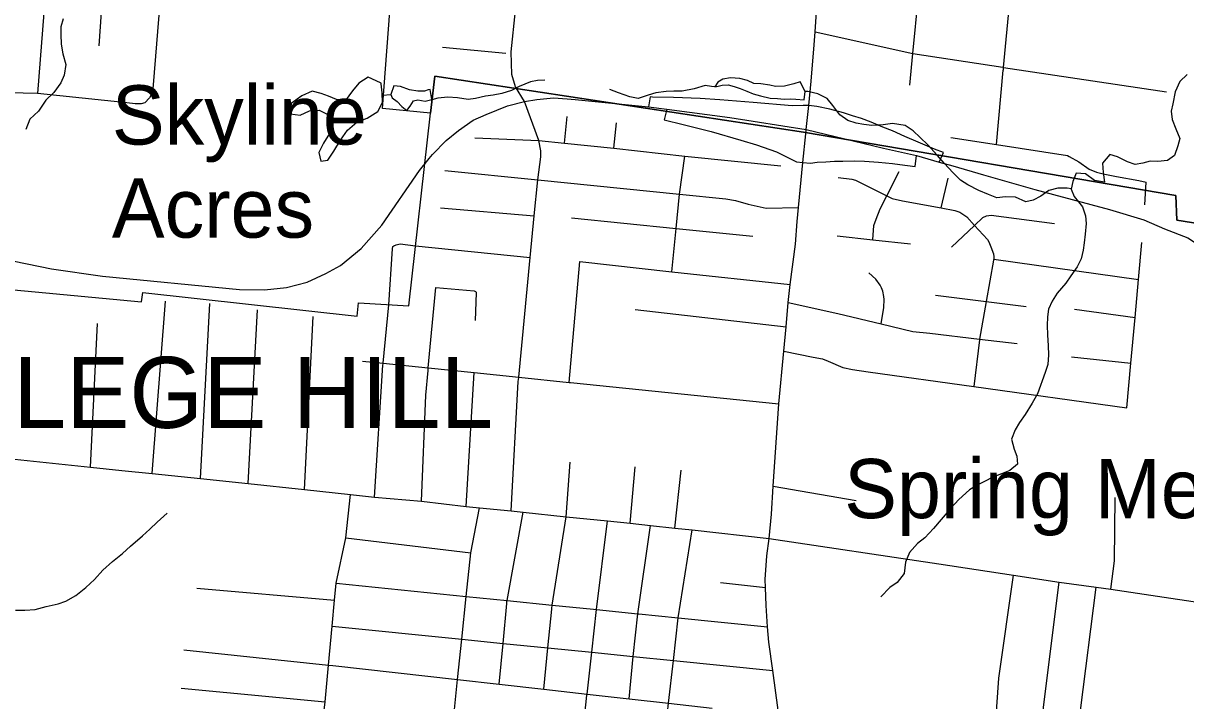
# Model space of a CAD drawing. Extents: x 0 to 69.5, y -4.5 to 22.
# Drawn here: x 5.421 to 6.973, y 15.023 to 15.927 of the extents above; entities that cross this region are included whole.
import ezdxf

# ---------------------------------------------------------------- set-up
doc = ezdxf.new("R2010")
doc.units = 0
for name, color, linetype in [('GM_X_City_Street', 7, 'Continuous'), ('GM_X_Corporation', 7, 'Continuous'), ('GM_X_Corporation_Text', 7, 'Continuous'), ('GM_X_Interchange_Ramps', 7, 'Continuous'), ('GM_X_Minor_Lake', 7, 'Continuous'), ('GM_X_Minor_River', 7, 'Continuous'), ('GM_X_State_Route', 7, 'Continuous'), ('GM_X_Township_Subdivision', 7, 'Continuous'), ('GM_X_Unincorporated_Text', 7, 'Continuous'), ('GM_X_US_Route', 7, 'Continuous')]:
    doc.layers.add(name, color=color, linetype=linetype)

msp = doc.modelspace()

# ---------------------------------------------------------------- linework, layer by layer
at = {"layer": 'GM_X_City_Street'}
for points in [[(6.0782, 15.8417), (6.073, 15.8584), (6.0723, 15.8887), (6.0782, 15.9436), (6.0848, 16.0117), (6.0879, 16.0415), (6.0881, 16.0439), (6.0947, 16.1212), (6.1032, 16.2159)], [(6.7292, 15.8641), (6.7295, 15.8678), (6.7378, 15.9562), (6.7561, 16.1506), (6.7562, 16.1518), (6.7563, 16.1521)], [(6.6042, 15.8442), (6.6083, 15.8863), (6.6157, 15.9635)], [(6.4779, 15.9151), (6.6083, 15.8863), (6.7283, 15.868), (6.7295, 15.8678), (6.9469, 15.8351)], [(5.9805, 15.8947), (6.0649, 15.8869)], [(6.7198, 15.7648), (6.7291, 15.864), (6.7292, 15.8641)], [(6.0823, 15.4541), (6.0823, 15.4546), (6.0976, 15.6143), (6.1029, 15.6697), (6.1076, 15.718), (6.1118, 15.7486), (6.1118, 15.7565), (6.1092, 15.7703), (6.0898, 15.8223), (6.0782, 15.8417)], [(6.1433, 15.7667), (6.147, 15.8022)], [(6.2091, 15.7601), (6.2127, 15.794)], [(6.0239, 15.7737), (6.1092, 15.7703), (6.1433, 15.7667), (6.2091, 15.7601), (6.3038, 15.7493), (6.432, 15.7365)], [(6.659, 15.7742), (6.7198, 15.7648), (6.8147, 15.7502), (6.8169, 15.749)], [(6.2868, 15.5953), (6.2923, 15.6531), (6.2967, 15.6989), (6.3038, 15.7493)], [(6.8169, 15.749), (6.8301, 15.7417), (6.8435, 15.7319), (6.8534, 15.7281), (6.8622, 15.7258), (6.88, 15.7225), (6.9102, 15.7169), (6.9197, 15.7146)], [(5.9837, 15.7305), (6.1076, 15.718), (6.2967, 15.6989), (6.3588, 15.6926), (6.3717, 15.6904), (6.3887, 15.6855), (6.4125, 15.68), (6.4555, 15.6809)], [(6.5085, 15.7208), (6.527, 15.7186), (6.5319, 15.7173), (6.5737, 15.6965), (6.5808, 15.693), (6.5944, 15.6897), (6.646, 15.6804), (6.6645, 15.6771), (6.6709, 15.6747), (6.6802, 15.6684), (6.6907, 15.6571), (6.7081, 15.6382), (6.7096, 15.6353), (6.7124, 15.6286), (6.716, 15.619), (6.7165, 15.615), (6.7163, 15.6122), (6.7162, 15.6106), (6.7064, 15.5556), (6.6974, 15.5054), (6.6972, 15.5043), (6.6897, 15.442)], [(6.5548, 15.6379), (6.5561, 15.6571), (6.5593, 15.6654), (6.5649, 15.6793), (6.5737, 15.6965), (6.5903, 15.7289)], [(6.646, 15.6804), (6.6555, 15.7199)], [(6.918, 15.6844), (6.9197, 15.7146)], [(5.9777, 15.6805), (6.1029, 15.6697)], [(6.1526, 15.6672), (6.2923, 15.6531), (6.3946, 15.6428)], [(6.66, 15.6282), (6.6907, 15.6571), (6.7019, 15.6676), (6.7065, 15.6697), (6.713, 15.6707), (6.7975, 15.6598)], [(6.5075, 15.643), (6.5548, 15.6379), (6.605, 15.6325)], [(5.9444, 15.6299), (6.0976, 15.6143)], [(6.436, 15.4891), (6.4755, 15.4814), (6.4876, 15.4789), (6.4951, 15.476), (6.5147, 15.4673), (6.5276, 15.4647), (6.5488, 15.4616), (6.6897, 15.442), (6.894, 15.4137), (6.8995, 15.4733), (6.905, 15.5343), (6.9097, 15.5848), (6.9142, 15.6343)], [(6.7163, 15.6122), (6.9097, 15.5848)], [(6.1494, 15.4477), (6.1639, 15.6088)], [(6.1639, 15.6088), (6.2868, 15.5953), (6.4444, 15.5782)], [(6.566, 15.5259), (6.5697, 15.5474), (6.5699, 15.558), (6.5695, 15.562), (6.5682, 15.5691), (6.5663, 15.5739), (6.5646, 15.5775), (6.5591, 15.5852), (6.5498, 15.5938)], [(5.9615, 15.4662), (5.9616, 15.467), (5.9716, 15.5742)], [(5.9716, 15.5742), (6.0228, 15.5697), (6.0236, 15.5694), (6.0244, 15.569), (6.0254, 15.568), (6.0257, 15.567), (6.0242, 15.5301)], [(6.6388, 15.5641), (6.7064, 15.5556), (6.7597, 15.5489)], [(5.5931, 15.326), (5.6109, 15.5559)], [(5.6577, 15.3193), (5.6701, 15.5527)], [(5.9013, 15.4722), (5.9014, 15.4732), (5.9091, 15.5509)], [(6.4421, 15.5541), (6.5083, 15.5396), (6.566, 15.5259), (6.6085, 15.5157), (6.6309, 15.5133), (6.6974, 15.5054), (6.7476, 15.4994)], [(5.7212, 15.3127), (5.7338, 15.5445)], [(5.7962, 15.3048), (5.8077, 15.5357)], [(6.2378, 15.5448), (6.4391, 15.5219)], [(6.8243, 15.5452), (6.905, 15.5343)], [(5.5108, 15.3345), (5.5201, 15.526)], [(5.8737, 15.4761), (5.9014, 15.4732), (5.9616, 15.467), (6.0227, 15.4607), (6.0823, 15.4546), (6.1494, 15.4477), (6.1516, 15.4475)], [(5.8897, 15.2946), (5.9011, 15.4706), (5.9013, 15.4722)], [(6.8199, 15.4818), (6.8995, 15.4733)], [(5.9524, 15.289), (5.9582, 15.4305), (5.9613, 15.4637), (5.9615, 15.4662)], [(6.012, 15.2821), (6.0227, 15.4607)], [(6.072, 15.2762), (6.0817, 15.4486), (6.0823, 15.4541)], [(6.1516, 15.4475), (6.1516, 15.4475), (6.4295, 15.4189)], [(5.4006, 15.3461), (5.5108, 15.3345), (5.5525, 15.3303), (5.5931, 15.326), (5.6577, 15.3193), (5.7212, 15.3127), (5.7962, 15.3048), (5.8577, 15.298), (5.8897, 15.2946), (5.9524, 15.289), (6.012, 15.2821), (6.03, 15.2801), (6.072, 15.2762), (6.0883, 15.2744), (6.1454, 15.2685), (6.2008, 15.2629), (6.2309, 15.2599), (6.2583, 15.2568), (6.2907, 15.2533), (6.3139, 15.2509), (6.4165, 15.2392), (6.6429, 15.2058), (6.7426, 15.1905), (6.8038, 15.1813), (6.853, 15.1746), (6.8725, 15.1716), (6.9082, 15.1664), (7.0179, 15.1499)], [(6.1265, 15.146), (6.1269, 15.1506), (6.1454, 15.2685), (6.1508, 15.3411)], [(6.2309, 15.2599), (6.2378, 15.3349)], [(6.2907, 15.2533), (6.2991, 15.3306)], [(6.4217, 15.3094), (6.5329, 15.2901)], [(5.7994, 14.7287), (5.8036, 14.7837), (5.8078, 14.8371), (5.8123, 14.8957), (5.8135, 14.9116), (5.8172, 14.9514), (5.8227, 15.0103), (5.8238, 15.0217), (5.8283, 15.0704), (5.8331, 15.1226), (5.8363, 15.1573), (5.8384, 15.1798), (5.8514, 15.2403), (5.8577, 15.298)], [(6.8725, 15.1716), (6.8776, 15.2094), (6.8785, 15.2943)], [(5.9646, 14.6836), (5.9672, 14.7104), (5.9726, 14.7656), (5.9779, 14.8204), (5.9835, 14.8784), (5.989, 14.9347), (5.9946, 14.9926), (5.9947, 14.9935), (6.0007, 15.0512), (6.0063, 15.1051), (6.0122, 15.1622), (6.0182, 15.2201), (6.03, 15.2801)], [(6.0666, 15.1554), (6.0668, 15.1567), (6.0883, 15.2744)], [(6.1663, 14.6603), (6.1668, 14.6642), (6.1712, 14.7045), (6.1712, 14.7102), (6.17, 14.7149), (6.1679, 14.7194), (6.1454, 14.7435), (6.144, 14.7461), (6.1438, 14.7474), (6.1436, 14.7485), (6.1444, 14.7549), (6.1495, 14.8036), (6.1556, 14.8611), (6.1616, 14.918), (6.1675, 14.9747), (6.1734, 15.0304), (6.1736, 15.0319), (6.1798, 15.0876), (6.1861, 15.1446), (6.2008, 15.2629)], [(6.2295, 15.0256), (6.2352, 15.082), (6.2411, 15.1391), (6.2583, 15.2568)], [(5.8514, 15.2403), (6.0182, 15.2201)], [(6.2769, 14.9701), (6.2824, 15.0197), (6.2887, 15.0766), (6.2951, 15.1336), (6.3139, 15.2509)], [(5.8384, 15.1798), (6.0122, 15.1622), (6.0668, 15.1567), (6.1269, 15.1506), (6.1821, 15.145), (6.1821, 15.145)], [(6.3515, 15.1805), (6.4116, 15.174)], [(6.7127, 14.9065), (6.7231, 15.053), (6.7426, 15.1905)], [(6.7735, 14.9063), (6.7826, 15.0145), (6.8038, 15.1813)], [(5.6527, 15.1731), (5.8363, 15.1573)], [(6.8236, 14.9014), (6.8322, 15.0099), (6.853, 15.1746)], [(6.0562, 15.045), (6.0614, 15.0995), (6.0664, 15.1526), (6.0666, 15.1554)], [(6.1159, 15.0383), (6.1213, 15.0935), (6.1264, 15.1451), (6.1265, 15.146)], [(6.1821, 15.145), (6.1861, 15.1446), (6.2411, 15.1391), (6.2427, 15.1389), (6.2427, 15.1389)], [(6.2427, 15.1389), (6.2951, 15.1336), (6.4145, 15.1215)], [(5.8331, 15.1226), (6.0063, 15.1051), (6.0614, 15.0995), (6.1213, 15.0935), (6.1798, 15.0876), (6.2352, 15.082), (6.2887, 15.0766), (6.4213, 15.0632)], [(5.6354, 15.0907), (5.8283, 15.0704), (5.8341, 15.0698)], [(5.8341, 15.0698), (5.8342, 15.0698), (6.0007, 15.0512), (6.0562, 15.045), (6.1159, 15.0383), (6.1736, 15.0319), (6.2295, 15.0256), (6.2824, 15.0197), (6.3407, 15.0132)], [(5.6316, 15.0398), (5.8238, 15.0217)]]:
    msp.add_lwpolyline(points, dxfattribs=at)
at = {"layer": 'GM_X_Corporation'}
for points in [[(7.1222, 15.6381), (6.9605, 15.6641), (6.9592, 15.6968), (6.4625, 15.7812), (5.9702, 15.8563), (5.9645, 15.8066), (5.9003, 15.8132), (5.9183, 16.0488)], [(5.3269, 14.8644), (5.36, 15.3466), (5.3844, 15.5735), (5.5787, 15.5551), (5.5807, 15.5674), (5.8665, 15.5358), (5.8686, 15.5537), (5.9354, 15.5498), (5.9645, 15.8066), (5.9702, 15.8563), (6.4625, 15.7812), (6.9592, 15.6968), (6.9605, 15.6641), (7.1222, 15.6381)]]:
    msp.add_lwpolyline(points, dxfattribs=at)
at = {"layer": 'GM_X_Interchange_Ramps'}
for points in [[(6.4694, 15.8172), (6.4619, 15.817), (6.4474, 15.8164), (6.3954, 15.8208), (6.3507, 15.8246), (6.3246, 15.8264), (6.2887, 15.8275), (6.261, 15.8282), (6.2579, 15.8284), (6.2556, 15.8154)], [(6.2798, 15.8121), (6.2763, 15.7978), (6.3019, 15.7916), (6.3392, 15.7822), (6.3789, 15.7709), (6.3996, 15.7643), (6.4265, 15.755), (6.4531, 15.7419), (6.4616, 15.741)], [(6.6435, 15.7414), (6.6494, 15.7541), (6.6373, 15.7588), (6.6154, 15.7682), (6.5976, 15.7757), (6.5811, 15.7831), (6.5681, 15.7882), (6.5527, 15.7947), (6.54, 15.7996), (6.5277, 15.8034), (6.5157, 15.8074), (6.4974, 15.8119), (6.48, 15.8155), (6.4694, 15.8172)], [(6.4616, 15.741), (6.4717, 15.74), (6.4805, 15.7414), (6.4924, 15.742), (6.5036, 15.7426), (6.5149, 15.7428), (6.531, 15.7431), (6.5436, 15.7426), (6.5627, 15.7412), (6.5811, 15.7395), (6.5911, 15.7383), (6.6115, 15.7357), (6.6133, 15.7501)]]:
    msp.add_lwpolyline(points, dxfattribs=at)
at = {"layer": 'GM_X_Minor_Lake'}
for points in [[(5.8922, 15.8501), (5.8815, 15.8546), (5.8687, 15.8466), (5.8605, 15.8365), (5.8508, 15.8234), (5.839, 15.8252), (5.8285, 15.8296), (5.8187, 15.8332), (5.8066, 15.8362), (5.7928, 15.83), (5.7785, 15.8197), (5.7771, 15.8057), (5.7907, 15.8039), (5.803, 15.81), (5.8159, 15.8109), (5.8283, 15.8045), (5.8338, 15.793), (5.8297, 15.7798), (5.8218, 15.7667), (5.8154, 15.7543), (5.8182, 15.7429), (5.8277, 15.7442), (5.8356, 15.7561), (5.8443, 15.7708), (5.8537, 15.7842), (5.8664, 15.7946), (5.8802, 15.8), (5.8941, 15.8088), (5.9005, 15.8208), (5.9, 15.8337), (5.8987, 15.8459), (5.8989, 15.8468)], [(5.8989, 15.8468), (5.8922, 15.8501)], [(5.9639, 15.8385), (5.9616, 15.8377), (5.9566, 15.8363), (5.9475, 15.8361), (5.9365, 15.8379), (5.9245, 15.8423), (5.9158, 15.8433), (5.9117, 15.8316), (5.9135, 15.8273), (5.9199, 15.8223), (5.9262, 15.8157), (5.9329, 15.8102), (5.9376, 15.8162), (5.9419, 15.8233), (5.9476, 15.8247), (5.9575, 15.8226), (5.9665, 15.8248)], [(6.4648, 15.8357), (6.4578, 15.8487), (6.4494, 15.8458), (6.4372, 15.8427), (6.425, 15.8422), (6.4175, 15.8439), (6.4054, 15.8457), (6.3963, 15.8463), (6.3876, 15.8503), (6.3774, 15.8531), (6.3649, 15.8538), (6.3546, 15.8521), (6.3481, 15.8481), (6.3441, 15.8417), (6.3487, 15.8428), (6.3537, 15.8442), (6.362, 15.8444), (6.37, 15.8423), (6.3779, 15.8395), (6.3869, 15.8362), (6.3952, 15.8326), (6.405, 15.8297), (6.4179, 15.8268), (6.4277, 15.8262), (6.4364, 15.8256), (6.4444, 15.8258), (6.452, 15.8253), (6.4634, 15.8246)], [(5.9665, 15.8248), (5.9639, 15.8385)], [(6.4634, 15.8246), (6.4648, 15.8357)]]:
    msp.add_lwpolyline(points, dxfattribs=at)
at = {"layer": 'GM_X_Minor_River'}
for points in [[(5.4741, 15.9327), (5.4712, 15.9221), (5.4713, 15.9115), (5.4714, 15.8989), (5.4737, 15.8859), (5.4776, 15.8718), (5.4757, 15.8574), (5.4713, 15.8472), (5.4618, 15.8345), (5.4513, 15.8241), (5.4411, 15.8095), (5.4298, 15.7988), (5.4245, 15.7848)], [(6.9744, 15.8585), (6.9647, 15.8492), (6.9587, 15.8353), (6.9552, 15.8194), (6.9531, 15.8096), (6.9543, 15.7981), (6.9594, 15.7858), (6.9647, 15.7728), (6.9622, 15.763), (6.9577, 15.7505), (6.9481, 15.7435), (6.9355, 15.7423), (6.9253, 15.7426), (6.9153, 15.7401), (6.905, 15.7385), (6.8948, 15.7418), (6.8817, 15.7486), (6.8715, 15.7515), (6.8617, 15.7399), (6.8626, 15.7277), (6.8642, 15.7148), (6.8509, 15.717), (6.8386, 15.726), (6.8264, 15.7267), (6.822, 15.7154), (6.8198, 15.7052), (6.8238, 15.6956), (6.8349, 15.682), (6.8387, 15.6697), (6.8396, 15.6595), (6.8385, 15.6454), (6.8371, 15.634)], [(6.1173, 15.8509), (6.1075, 15.8504), (6.0979, 15.8487), (6.0829, 15.8422), (6.0725, 15.8368), (6.0599, 15.8329), (6.0481, 15.8309), (6.0378, 15.8296), (6.0248, 15.8265), (6.0149, 15.8249), (6.0005, 15.8271), (5.9876, 15.8282), (5.9743, 15.8266), (5.9663, 15.8247)], [(6.3441, 15.8417), (6.3396, 15.8425), (6.3313, 15.8438), (6.3166, 15.8392), (6.3005, 15.8362), (6.2895, 15.836), (6.2792, 15.8355), (6.2655, 15.834), (6.2552, 15.8308), (6.2418, 15.8262), (6.2304, 15.8287), (6.2153, 15.8337), (6.2041, 15.8385)], [(5.9119, 15.8312), (5.9001, 15.8303)], [(6.82, 15.7059), (6.8142, 15.7069), (6.802, 15.7068), (6.7898, 15.7036), (6.779, 15.6959), (6.769, 15.6908), (6.759, 15.6884), (6.7455, 15.6948), (6.7318, 15.6952), (6.7204, 15.6939), (6.7095, 15.6984), (6.6963, 15.7036), (6.6817, 15.7112), (6.6719, 15.7172), (6.6619, 15.7277), (6.6508, 15.7394), (6.6408, 15.7506), (6.6282, 15.7646), (6.6182, 15.7744), (6.6086, 15.7834), (6.5981, 15.7901), (6.5811, 15.7932), (6.5689, 15.7912), (6.5536, 15.7904), (6.543, 15.7918), (6.5328, 15.7936), (6.5215, 15.7969), (6.511, 15.8044), (6.5015, 15.8168), (6.4941, 15.8265), (6.4817, 15.8325), (6.4681, 15.8355), (6.4648, 15.8357)], [(6.8371, 15.634), (6.8357, 15.6242), (6.8332, 15.6125), (6.8276, 15.6016), (6.8193, 15.5896), (6.8126, 15.5799), (6.8009, 15.5665), (6.7945, 15.556), (6.7894, 15.5454), (6.788, 15.5352), (6.7877, 15.5234), (6.7881, 15.5109), (6.7889, 15.4964), (6.7894, 15.4842), (6.7883, 15.4713), (6.785, 15.4607), (6.7748, 15.4325), (6.7677, 15.4201), (6.7582, 15.4047), (6.7507, 15.3943), (6.7448, 15.3845), (6.7399, 15.3721), (6.7438, 15.3587), (6.7473, 15.3491), (6.7482, 15.3384), (6.7378, 15.3303), (6.7266, 15.3256), (6.7143, 15.3206), (6.7047, 15.3159), (6.6951, 15.3108), (6.6839, 15.3042), (6.6696, 15.2916), (6.659, 15.2797), (6.6461, 15.2648), (6.6359, 15.2529), (6.6242, 15.2403), (6.6145, 15.2325), (6.604, 15.2206), (6.5987, 15.2078), (6.5968, 15.1926), (6.5874, 15.1807), (6.5778, 15.1741), (6.5657, 15.1615)], [(5.4108, 15.1439), (5.423, 15.144), (5.4367, 15.1445), (5.4516, 15.1487), (5.4677, 15.1524), (5.478, 15.156), (5.4911, 15.1633), (5.5043, 15.174), (5.5159, 15.1847), (5.5273, 15.197), (5.5401, 15.2085), (5.5533, 15.2192), (5.5641, 15.2292), (5.5801, 15.2429), (5.5898, 15.2518), (5.5995, 15.2614), (5.6131, 15.2733)]]:
    msp.add_lwpolyline(points, dxfattribs=at)
at = {"layer": 'GM_X_State_Route'}
for points in [[(5.9627, 15.7461), (5.9671, 15.7516), (5.9855, 15.7703), (6.002, 15.7838), (6.0217, 15.7973), (6.039, 15.8048), (6.0674, 15.8167), (6.0898, 15.8223), (6.1065, 15.8251), (6.1289, 15.827), (6.1468, 15.8257)], [(6.1468, 15.8257), (6.1578, 15.8249), (6.2556, 15.8154), (6.2798, 15.8121), (6.364, 15.8012), (6.466, 15.7849)], [(4.6332, 15.782), (4.7176, 15.7753), (4.959, 15.7532), (4.9968, 15.7493), (5.0379, 15.742), (5.0859, 15.7305), (5.1254, 15.7187), (5.201, 15.6901), (5.3286, 15.6339), (5.3828, 15.616), (5.3914, 15.6131), (5.4588, 15.599), (5.5268, 15.5892), (5.7096, 15.5717), (5.7429, 15.5711), (5.7725, 15.5744), (5.8001, 15.5813), (5.8247, 15.5928), (5.8445, 15.6036), (5.8718, 15.6263), (5.8997, 15.6575), (5.9497, 15.7302), (5.9627, 15.7461)], [(6.466, 15.7849), (6.5543, 15.7638)], [(6.5543, 15.7638), (6.5692, 15.7602), (6.6133, 15.7501), (6.6435, 15.7414), (6.6616, 15.7363), (6.7026, 15.7247), (6.7712, 15.7051), (6.871, 15.6782), (6.9165, 15.6643), (6.9444, 15.6525), (6.9756, 15.6403), (7.0026, 15.6225), (7.0332, 15.6017), (7.062, 15.578), (7.2557, 15.428), (7.3428, 15.3613), (7.3665, 15.3432), (7.375, 15.3384)]]:
    msp.add_lwpolyline(points, dxfattribs=at)
at = {"layer": 'GM_X_Township_Subdivision'}
for points in [[(5.5845, 16.3492), (5.5825, 16.3306), (5.5813, 16.3253), (5.5789, 16.3198), (5.5641, 16.3), (5.5609, 16.2934), (5.5585, 16.2827), (5.5577, 16.2722), (5.5503, 16.1649), (5.5478, 16.1247), (5.5451, 16.1168), (5.5399, 16.1092), (5.4864, 16.0372), (5.4518, 15.9911), (5.4511, 15.9791), (5.4502, 15.9637), (5.4401, 15.8331)], [(5.5577, 16.2722), (5.6156, 16.2678), (5.6217, 16.2658), (5.6252, 16.2617), (5.6075, 16.0089), (5.5945, 15.8445), (5.5933, 15.8347), (5.5895, 15.8274), (5.5833, 15.8204), (5.5783, 15.8191), (5.5702, 15.819), (5.5594, 15.8204), (5.4401, 15.8331), (5.4019, 15.8337)], [(5.5221, 15.8965), (5.5254, 15.9416), (5.5264, 15.9549), (5.5305, 15.9634), (5.5498, 15.9907), (5.5575, 15.9997), (5.5662, 16.0087), (5.5734, 16.011), (5.586, 16.0105), (5.6075, 16.0089)], [(5.9091, 15.5509), (5.9136, 15.6256), (5.9144, 15.6287), (5.9156, 15.6298)], [(5.9156, 15.6298), (5.9186, 15.6313), (5.924, 15.6324), (5.9444, 15.6299)]]:
    msp.add_lwpolyline(points, dxfattribs=at)
at = {"layer": 'GM_X_US_Route'}
for points in [[(6.4766, 15.898), (6.4779, 15.9151), (6.4804, 15.9485)], [(6.4654, 15.7791), (6.466, 15.7849), (6.4694, 15.8172), (6.4727, 15.8496), (6.4766, 15.898)], [(6.454, 15.6623), (6.4555, 15.6809), (6.4616, 15.741), (6.4654, 15.7791)], [(6.4285, 15.0103), (6.4213, 15.0632), (6.416, 15.1009), (6.4145, 15.1215), (6.4124, 15.1501), (6.4116, 15.174), (6.4112, 15.1847), (6.4135, 15.2162), (6.4165, 15.2392), (6.4198, 15.2719), (6.4217, 15.3094), (6.4295, 15.4189), (6.436, 15.4891), (6.4391, 15.5219), (6.4421, 15.5541), (6.4444, 15.5782), (6.4517, 15.6318), (6.454, 15.6623)]]:
    msp.add_lwpolyline(points, dxfattribs=at)

# ---------------------------------------------------------------- texts
at = {"layer": 'GM_X_Corporation_Text'}
msp.add_text('NORTH COLLEGE HILL', height=0.094697, rotation=0, dxfattribs=at).set_placement((4.662, 15.3869))
at = {"layer": 'GM_X_Unincorporated_Text'}
for s, height, p in [('Skyline', 0.07898, (5.5392, 15.7649)), ('Acres', 0.07898, (5.5392, 15.6407)), ('Spring Meadows', 0.078977, (6.5167, 15.2665))]:
    msp.add_text(s, height=height, rotation=0, dxfattribs=at).set_placement(p)

doc.saveas('drawing.dxf')
